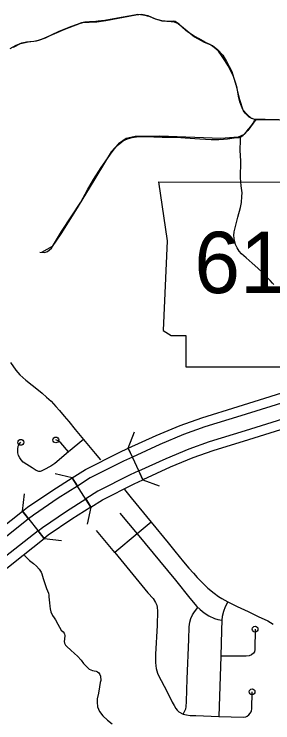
# Model space of a CAD drawing. Extents: x 670147 to 673275, y 705573 to 707613.
# Drawn here: x 671434.3 to 671478.7, y 706128.4 to 706250.4 of the extents above; entities that cross this region are included whole.
import ezdxf

# ---------------------------------------------------------------- set-up
doc = ezdxf.new("R2010")
doc.units = 0
for name, color, linetype in [('10', 7, 'Continuous'), ('21', 7, 'Continuous'), ('32', 7, 'Continuous'), ('33', 7, 'Continuous'), ('34', 7, 'Continuous'), ('35', 7, 'Continuous'), ('39', 7, 'Continuous'), ('45', 7, 'Continuous')]:
    doc.layers.add(name, color=color, linetype=linetype)

msp = doc.modelspace()

# ---------------------------------------------------------------- linework, layer by layer
at = {"layer": '10'}
for p, q in [((671454.59, 706174.13), (671453.88, 706175.65)), ((671456.39, 706170.2), (671455.69, 706171.73)), ((671456.39, 706170.2), (671455.69, 706171.73)), ((671445.14, 706169.14), (671444.24, 706170.56)), ((671439.39, 706160.1), (671438.35, 706161.41))]:
    msp.add_line(p, q, dxfattribs=at)
for points in [[(671453.88, 706175.65), (671458.66, 706177.85), (671462.8, 706179.58), (671466.51, 706180.9), (671472.76, 706182.82), (671483.96, 706186.3), (671501.43, 706191.69), (671522.01, 706198.06), (671521.45, 706196.13)], [(671521.45, 706196.13), (671501.92, 706190.09), (671484.46, 706184.7), (671473.26, 706181.22), (671467.04, 706179.3), (671463.4, 706178.01), (671459.33, 706176.31), (671454.59, 706174.13)], [(671455.69, 706171.73), (671460.39, 706173.89), (671464.35, 706175.54), (671467.87, 706176.8), (671474.04, 706178.7), (671485.24, 706182.18), (671502.7, 706187.56), (671520.57, 706193.09), (671520.01, 706191.16)], [(671520.01, 706191.16), (671503.2, 706185.96), (671485.74, 706180.57), (671474.53, 706177.09), (671468.4, 706175.2), (671464.96, 706173.98), (671461.07, 706172.36), (671456.39, 706170.2)], [(671444.24, 706170.56), (671446.51, 706171.99), (671452.3, 706174.93), (671453.88, 706175.65)], [(671454.59, 706174.13), (671453.03, 706173.41), (671447.34, 706170.53), (671445.14, 706169.14)], [(671455.69, 706171.73), (671454.18, 706171.04), (671448.64, 706168.23), (671446.55, 706166.91)], [(671435.67, 706164.81), (671436.56, 706165.51), (671440.89, 706168.44), (671444.24, 706170.56)], [(671444.24, 706170.56), (671445.14, 706169.14), (671441.81, 706167.04), (671437.55, 706164.15), (671436.71, 706163.49), (671435.67, 706164.81)], [(671447.45, 706165.49), (671449.47, 706166.77), (671454.91, 706169.52), (671456.39, 706170.2)], [(671438.35, 706161.41), (671439.11, 706162.02), (671443.26, 706164.83), (671446.55, 706166.91), (671447.45, 706165.49)], [(671427.91, 706158.65), (671430.09, 706160.4), (671435.67, 706164.81)], [(671447.45, 706165.49), (671444.18, 706163.42), (671440.11, 706160.66), (671439.39, 706160.1), (671438.35, 706161.41)], [(671436.71, 706163.49), (671431.13, 706159.08), (671428.96, 706157.34)], [(671438.35, 706161.41), (671432.77, 706157.01), (671430.6, 706155.28)], [(671431.65, 706153.97), (671433.82, 706155.7), (671439.39, 706160.1)]]:
    msp.add_lwpolyline(points, dxfattribs=at)
at = {"layer": '21'}
for p, q in [((671459.05, 706221.47), (671460.58, 706211.32)), ((671460.58, 706211.32), (671459.9, 706195.92)), ((671459.9, 706195.92), (671461.25, 706195.07)), ((671461.25, 706195.07), (671463.79, 706195.07)), ((671463.79, 706195.07), (671463.79, 706189.66)), ((671463.79, 706189.66), (671485.11, 706189.66))]:
    msp.add_line(p, q, dxfattribs=at)
msp.add_lwpolyline([(671459.05, 706221.47), (671489.48, 706221.45)], dxfattribs=at)
at = {"layer": '32'}
for points in [[(671454.94, 706250.2), (671452.02, 706249.68), (671449.85, 706249.28), (671448.7, 706249.12), (671447.9, 706249.05), (671447.23, 706249.04), (671446.43, 706248.98), (671445.84, 706248.84), (671445.08, 706248.59), (671443.96, 706248.17), (671441.92, 706247.36), (671440.59, 706246.72), (671439.56, 706246.24), (671438.42, 706245.83), (671437.64, 706245.66), (671436.95, 706245.59), (671436.38, 706245.53), (671435.88, 706245.43), (671435.49, 706245.34), (671435.09, 706245.19), (671434.55, 706244.95), (671433.51, 706244.37)], [(671482.17, 706232.09), (671477.42, 706232.2), (671476.05, 706232.23), (671475.71, 706232.25), (671475.45, 706232.31), (671475.03, 706232.44), (671474.67, 706232.63), (671474.31, 706232.99), (671473.97, 706233.33), (671473.72, 706233.72), (671473.49, 706234.24), (671473.25, 706234.8), (671473.08, 706235.25), (671472.85, 706236.23), (671472.58, 706237.62), (671472.36, 706238.44), (671471.95, 706239.6), (671471.54, 706240.61), (671471.08, 706241.47), (671470.59, 706242.23), (671469.91, 706243.26), (671469.39, 706243.97), (671469.01, 706244.32), (671468.45, 706244.8), (671467.9, 706245.14), (671467.06, 706245.56), (671465.95, 706246.16), (671465.06, 706246.69), (671464.22, 706247.19), (671463.76, 706247.56), (671463.08, 706248.16), (671462.63, 706248.65), (671462.3, 706248.89), (671461.92, 706249.08), (671461.58, 706249.15), (671461.24, 706249.11), (671460.75, 706249.08), (671460.2, 706249.14), (671459.65, 706249.22), (671459.26, 706249.31), (671458.56, 706249.52), (671457.65, 706249.88), (671457.21, 706250.03), (671456.81, 706250.14), (671456.36, 706250.2), (671455.96, 706250.25), (671455.53, 706250.27), (671454.94, 706250.2)]]:
    msp.add_lwpolyline(points, dxfattribs=at)
at = {"layer": '33'}
for points in [[(671433.6, 706190.42), (671434.55, 706189.07), (671435.24, 706188.29), (671435.72, 706187.79), (671436.23, 706187.35), (671437.36, 706186.5), (671438.44, 706185.66), (671439.07, 706185.13), (671439.82, 706184.44), (671440.6, 706183.74), (671441.42, 706182.85), (671442.05, 706182.13), (671442.85, 706181.19), (671443.66, 706180.25), (671444.76, 706178.88), (671446.15, 706177.15), (671448.2, 706174.72), (671449.1, 706173.62)], [(671446.15, 706177.15), (671443.62, 706175.02), (671441.23, 706173.02), (671440.58, 706172.57), (671439.33, 706171.9), (671438.91, 706171.69), (671438.71, 706171.62), (671438.49, 706171.64), (671438.06, 706171.81), (671437.36, 706172.29), (671436.44, 706172.83), (671435.82, 706173.25), (671435.44, 706173.67), (671435.2, 706174.01), (671434.99, 706174.41), (671434.89, 706174.85), (671434.87, 706175.5), (671434.94, 706176.02), (671435.08, 706176.34), (671435.39, 706176.66)], [(671443.62, 706175.02), (671442.29, 706176.55), (671441.82, 706176.9), (671441.42, 706177.07)], [(671453.2, 706168.57), (671454.38, 706167.13)], [(671454.38, 706167.13), (671457.81, 706162.92), (671460.73, 706159.37), (671461.87, 706157.95), (671463.39, 706156.1), (671464.32, 706155.02), (671465.12, 706154.12), (671465.73, 706153.42), (671466.43, 706152.68), (671466.99, 706152.11), (671467.58, 706151.55), (671468.64, 706150.68), (671469.39, 706150.14), (671469.95, 706149.76), (671470.99, 706149.21), (671472.63, 706148.43), (671474.48, 706147.52), (671476.2, 706146.71), (671477.86, 706145.92), (671478.81, 706145.34)], [(671452.45, 706164.46), (671455.41, 706160.9)], [(671457.81, 706162.92), (671455.41, 706160.9), (671451.58, 706157.7)], [(671451.58, 706157.7), (671448.39, 706161.49)], [(671455.41, 706160.9), (671462.02, 706152.93), (671464.48, 706149.84), (671465.66, 706148.41), (671466.22, 706147.9), (671466.93, 706147.33), (671467.74, 706146.81), (671468.7, 706146.36), (671469.26, 706146.19), (671469.97, 706146.07)], [(671451.58, 706157.7), (671457.24, 706150.77), (671458.13, 706149.77), (671458.57, 706149.12), (671458.79, 706148.66), (671458.86, 706148.22), (671458.89, 706147.65), (671458.82, 706145.15), (671458.58, 706140.2), (671458.58, 706138.76), (671458.6, 706138.19), (671458.66, 706137.73), (671458.8, 706137.33), (671458.93, 706136.92), (671459.14, 706136.39), (671459.53, 706135.67), (671460.54, 706133.72), (671461.44, 706131.92), (671461.76, 706131.34), (671462.04, 706130.85), (671462.27, 706130.55), (671462.58, 706130.27), (671463.29, 706129.89), (671463.88, 706129.75), (671464.5, 706129.65), (671465.51, 706129.62), (671469.44, 706129.48)], [(671470.99, 706149.21), (671470.56, 706148.35), (671470.25, 706147.53), (671470.05, 706146.67), (671469.97, 706146.07), (671469.94, 706144.29), (671469.79, 706139.87), (671469.44, 706129.48)], [(671463.29, 706129.89), (671463.61, 706130.43), (671463.77, 706130.77), (671463.86, 706131.14), (671463.89, 706132.07), (671464.03, 706135.96), (671464.28, 706142.7), (671464.34, 706144.88), (671464.45, 706145.7), (671464.62, 706146.36), (671464.9, 706146.95), (671465.27, 706147.49), (671465.82, 706148.25)], [(671475.69, 706144.51), (671475.63, 706141), (671475.57, 706140.6), (671475.41, 706140.35), (671475.1, 706140.1), (671474.67, 706139.92), (671474.16, 706139.84), (671473.21, 706139.84), (671469.79, 706139.87)], [(671469.44, 706129.48), (671473.7, 706129.35), (671474.07, 706129.39), (671474.34, 706129.55), (671474.62, 706129.75), (671474.85, 706130.03), (671475, 706130.28), (671475.08, 706130.46), (671475.13, 706130.8), (671475.17, 706133.73)]]:
    msp.add_lwpolyline(points, dxfattribs=at)
for centre in [(671435.39, 706176.66), (671441.42, 706177.07), (671475.69, 706144.51), (671475.17, 706133.73)]:
    msp.add_circle(centre, 0.5, dxfattribs=at)
at = {"layer": '34'}
for points in [[(671434.15, 706244.69), (671435.36, 706245.32), (671436.64, 706245.6), (671438.11, 706245.74), (671439.11, 706246.13), (671442.94, 706247.8), (671445.64, 706248.83), (671446.3, 706248.96), (671447.17, 706248.99), (671448.49, 706249.04), (671449.99, 706249.27), (671455.19, 706250.22), (671456.18, 706250.35), (671457.22, 706250.15), (671458.38, 706249.59), (671459.64, 706249.22), (671460.49, 706249.14), (671461.25, 706249.11), (671461.76, 706249.03), (671462.46, 706248.75), (671463.39, 706247.98), (671465.28, 706246.46), (671466.94, 706245.56), (671468.35, 706244.94), (671469.3, 706244.24), (671470.15, 706243.28), (671470.8, 706242.23), (671471.67, 706240.46), (671472.35, 706238.2), (671472.99, 706235.64), (671473.61, 706233.89), (671474.31, 706233.1), (671475.02, 706232.48), (671475.83, 706232.23), (671478.2, 706232.2), (671488.68, 706231.89)], [(671475.83, 706232.23), (671474.46, 706230.31), (671473.82, 706229.67), (671472.78, 706229.18), (671469.78, 706228.93), (671459.33, 706229.37), (671455.09, 706229.28), (671453.51, 706228.98), (671452.18, 706228.04), (671450.95, 706226.66), (671447.15, 706220.4), (671444.78, 706216.55), (671442.27, 706212.55), (671440.79, 706210.38), (671438.97, 706209.35)]]:
    msp.add_lwpolyline(points, dxfattribs=at)
at = {"layer": '35'}
for points in [[(671435.95, 706157.35), (671436.1, 706157.13), (671436.91, 706156.32), (671437.55, 706155.8), (671438.07, 706155.37), (671438.55, 706154.81), (671438.9, 706154.31), (671439.02, 706154), (671439.12, 706153.65), (671439.25, 706153.21), (671439.6, 706152.19), (671439.83, 706151.5), (671440.16, 706150.72), (671440.22, 706150.34), (671440.24, 706150.07), (671440.25, 706149.53), (671440.31, 706149.04), (671440.37, 706148.48), (671440.45, 706148.02), (671440.53, 706147.48), (671440.83, 706146.84), (671441.12, 706146.45), (671441.36, 706146.13), (671441.76, 706145.37)], [(671441.76, 706145.37), (671442.35, 706144.36), (671442.66, 706144.03), (671442.84, 706143.82), (671442.91, 706143.62), (671442.95, 706143.39), (671442.88, 706142.81), (671442.84, 706142.37), (671442.88, 706142.1), (671443.05, 706141.77), (671443.28, 706141.5), (671444.02, 706140.88), (671444.61, 706140.34), (671445.14, 706139.87), (671445.77, 706139.18), (671446.16, 706138.62), (671446.49, 706138.23), (671446.8, 706137.94), (671447.16, 706137.61), (671447.71, 706137.4), (671448.01, 706137.32), (671448.38, 706137.27), (671448.58, 706137.17), (671448.81, 706136.98), (671448.96, 706136.71), (671449.1, 706136.43), (671449.15, 706135.68), (671449.06, 706135.35), (671448.94, 706134.57), (671448.73, 706133.51), (671448.5, 706132.52), (671448.52, 706131.92), (671448.59, 706131.13), (671448.94, 706130.32), (671449.5, 706129.6), (671450.28, 706128.83), (671451.11, 706128.23)]]:
    msp.add_lwpolyline(points, dxfattribs=at)
at = {"layer": '39'}
for p, q in [((671453.88, 706175.65), (671454.92, 706178.47)), ((671453.88, 706175.65), (671456.39, 706170.2)), ((671444.24, 706170.56), (671441.31, 706171.22)), ((671447.45, 706165.49), (671444.24, 706170.56)), ((671456.39, 706170.2), (671459.21, 706169.16)), ((671435.67, 706164.81), (671436.02, 706167.79)), ((671435.67, 706164.81), (671439.39, 706160.1)), ((671447.45, 706165.49), (671446.79, 706162.56)), ((671439.39, 706160.1), (671442.37, 706159.75))]:
    msp.add_line(p, q, dxfattribs=at)
at = {"layer": '45'}
for points in [[(671438.64, 706209.39), (671439.46, 706209.34), (671439.97, 706209.53), (671440.68, 706210.1), (671442.39, 706212.92), (671445.72, 706218.01), (671446.85, 706220.09), (671447.89, 706221.9), (671449.19, 706223.98), (671450.29, 706225.53), (671451.12, 706226.65), (671451.76, 706227.49), (671452.38, 706228.05), (671452.83, 706228.43), (671453.33, 706228.75), (671453.91, 706228.97), (671454.54, 706229.13), (671455.31, 706229.24), (671456.76, 706229.28), (671459.72, 706229.2), (671460.99, 706229.19), (671462.11, 706229.16), (671463.67, 706229.09), (671466.2, 706228.92), (671468.13, 706228.81), (671469.46, 706228.81), (671470.23, 706228.85), (671470.96, 706228.92), (671472.1, 706229.04), (671472.93, 706229.13), (671473.19, 706229.22), (671473.37, 706229.3), (671473.63, 706229.54), (671474.27, 706230.22), (671474.93, 706231.04), (671475.35, 706231.62), (671475.6, 706232.03), (671475.71, 706232.25)], [(671478.7, 706204.07), (671478.27, 706204.52), (671477.59, 706205.23), (671476.97, 706205.87), (671476.19, 706206.62), (671475.16, 706207.5), (671474.13, 706208.4), (671473.35, 706209.13), (671472.97, 706209.58), (671472.59, 706210.14), (671472.33, 706210.69), (671472.14, 706211.35), (671472.07, 706211.82), (671472.06, 706212.26), (671472.11, 706212.87), (671472.17, 706213.12), (671472.32, 706213.81), (671472.71, 706215.4), (671473.16, 706217.06), (671473.34, 706217.95), (671473.43, 706218.95), (671473.45, 706219.58), (671473.3, 706220.79), (671473.17, 706222.17), (671473.21, 706225.04), (671473.13, 706226.97), (671473.19, 706228.69), (671473.19, 706229.22)], [(671478.94, 706203.83), (671478.7, 706204.07)]]:
    msp.add_lwpolyline(points, dxfattribs=at)

# ---------------------------------------------------------------- texts
at = {"layer": '21'}
msp.add_text('612', height=10.56, dxfattribs=at).set_placement((671465.24, 706202.34))

doc.saveas('drawing.dxf')
